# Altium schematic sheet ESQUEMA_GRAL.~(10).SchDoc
size A3
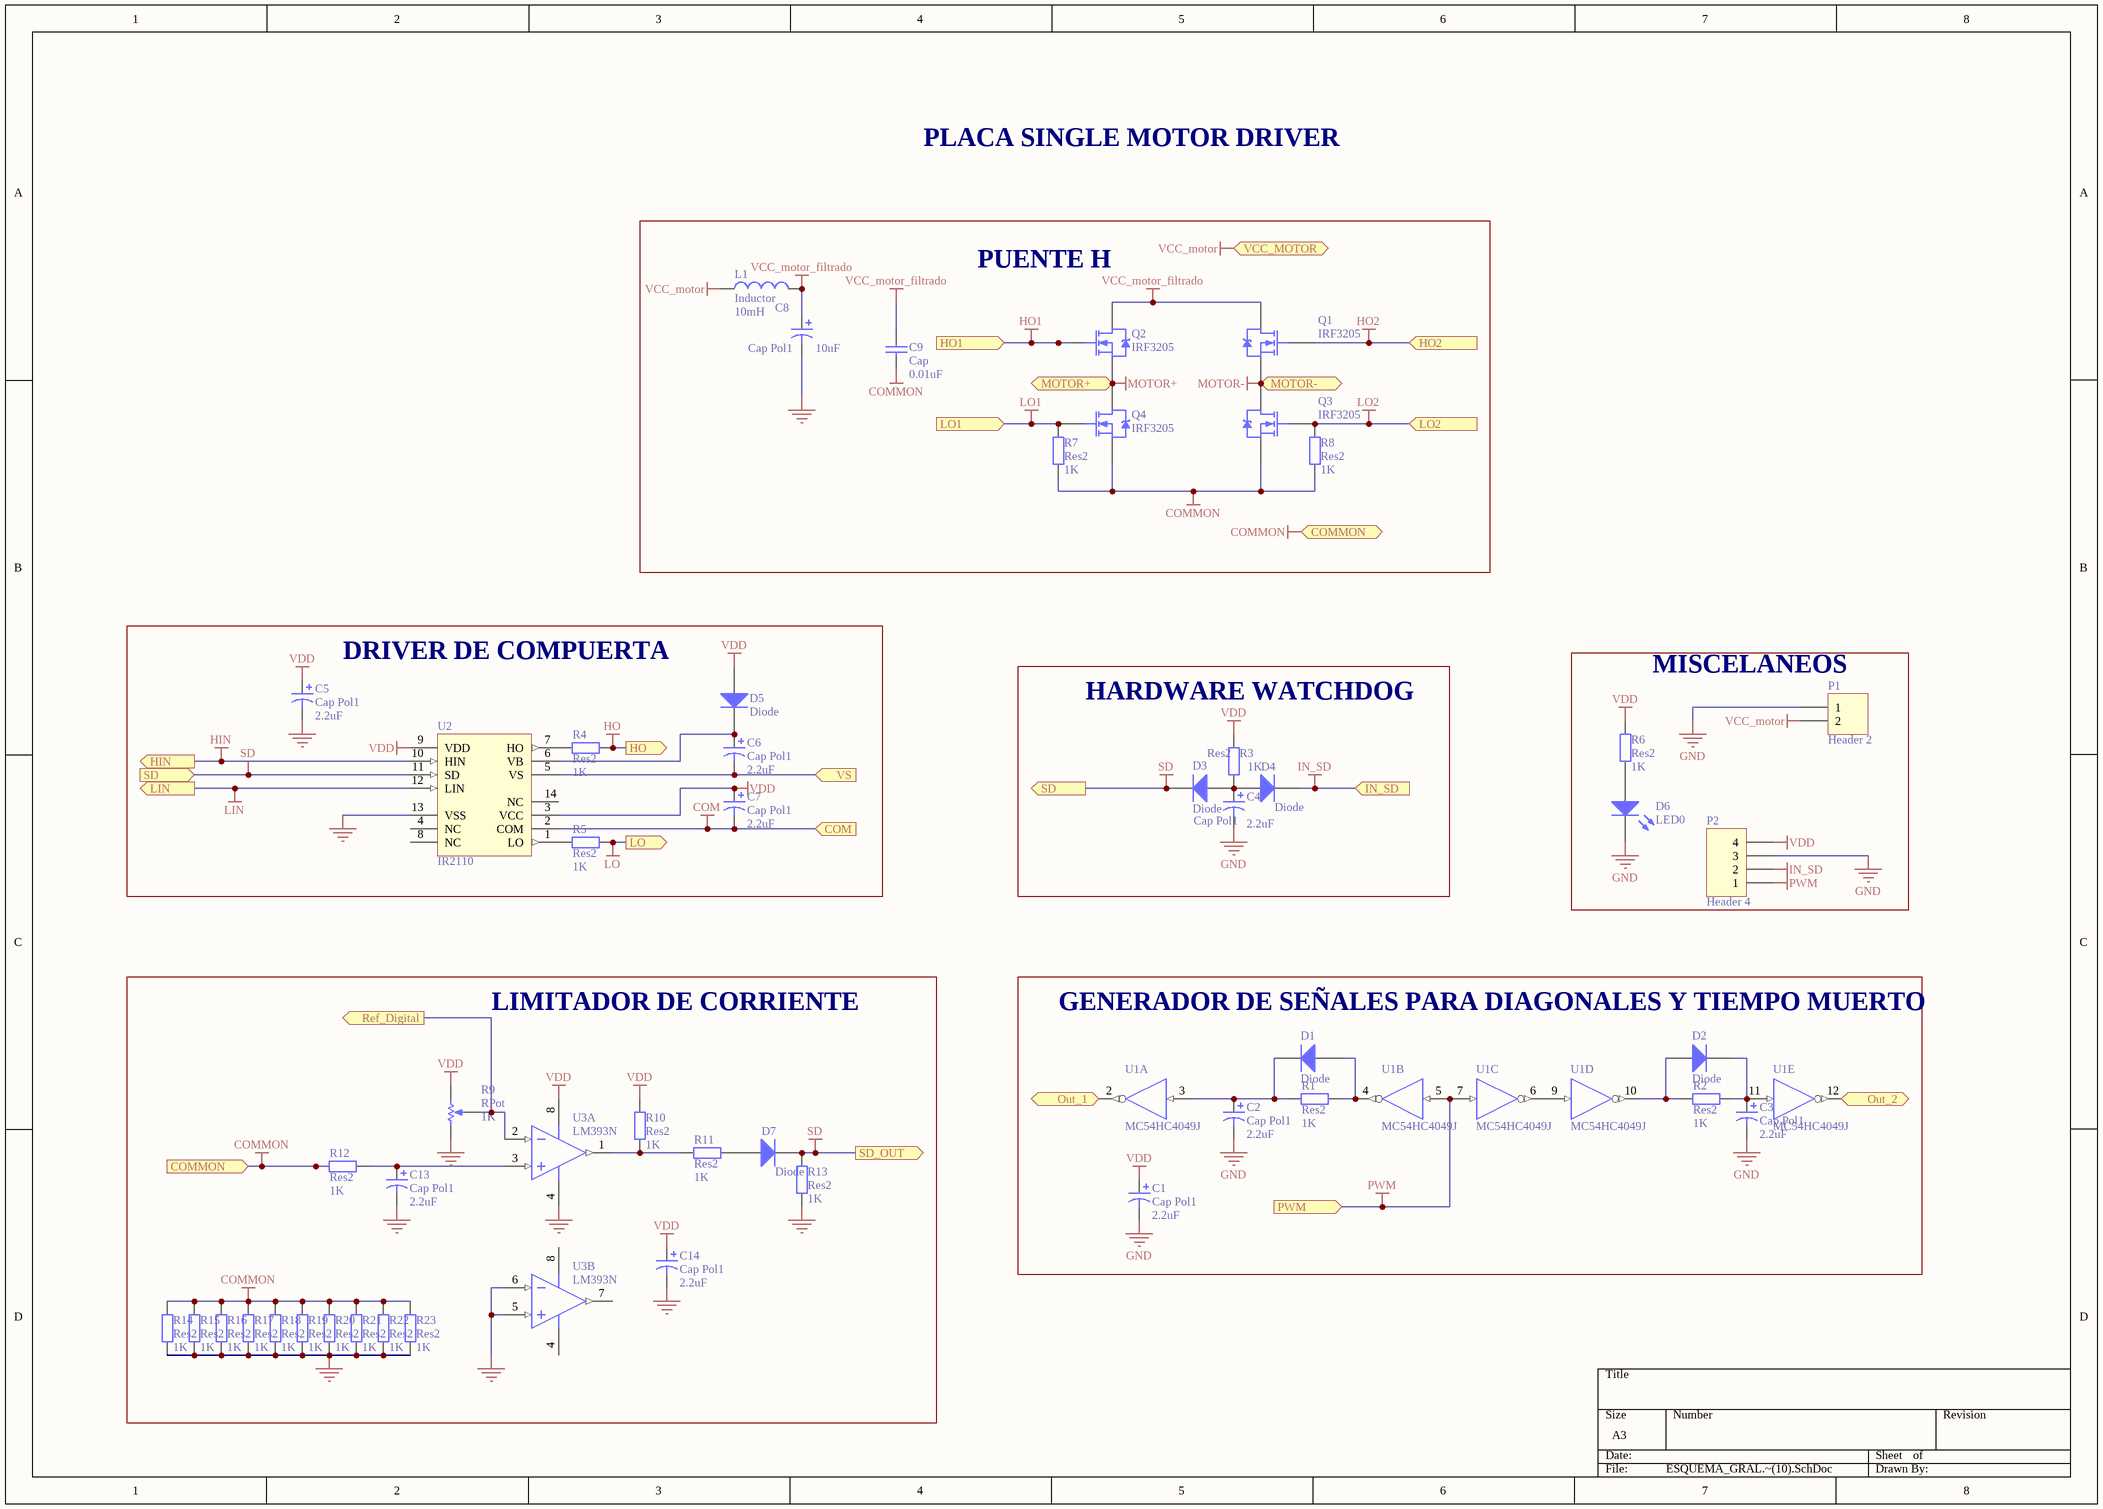
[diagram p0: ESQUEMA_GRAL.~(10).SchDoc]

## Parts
C1  Cap Pol1  value 2.2uF  [CAPPR2.5-6.3X5]
C2  Cap Pol1  value 2.2uF  [CAPPR2.5-6.3X5]
C3  Cap Pol1  value 2.2uF  [CAPPR2.5-6.3X5]
C4  Cap Pol1  value 2.2uF  [CAPPR2.5-6.3X5]
C5  Cap Pol1  value 2.2uF  [CAPPR2.5-6.3X5]
C6  Cap Pol1  value 2.2uF  [CAPPR2.5-6.3X5]
C7  Cap Pol1  value 2.2uF  [CAPPR2.5-6.3X5]
C8  Cap Pol1  value 10uF  [CAPPR5-13X16]
C9  Cap  value 0.01uF  [RAD-0.2]
C13  Cap Pol1  value 2.2uF  [CAPPR2.5-6.3X5]
C14  Cap Pol1  value 2.2uF  [CAPPR2.5-6.3X5]
D1  Diode  [DO-204AL]
D2  Diode  [DO-204AL]
D3  Diode  [DO-204AL]
D4  Diode  [DO-204AL]
D5  Diode  [DO-204AL]
D6  LED0  [CAPPR2.5-6.3X5]
D7  Diode  [DO-204AL]
L1  Inductor  value 10mH  [bobina_Choque]
P1  Header 2  [pwheader1x2]
P2  Header 4  [HDR1X5]
Q1  IRF3205  [TO-220AB]
Q2  IRF3205  [TO-220AB]
Q3  IRF3205  [TO-220AB]
Q4  IRF3205  [TO-220AB]
R1  Res2  value 1K  [AXIAL-0.3]
R2  Res2  value 1K  [AXIAL-0.3]
R3  Res2  value 1K  [AXIAL-0.3]
R4  Res2  value 1K  [AXIAL-0.3]
R5  Res2  value 1K  [AXIAL-0.3]
R6  Res2  value 1K  [AXIAL-0.3]
R7  Res2  value 1K  [AXIAL-0.3]
R8  Res2  value 1K  [AXIAL-0.3]
R9  RPot  value 1K  [VR5]
R10  Res2  value 1K  [AXIAL-0.3]
R11  Res2  value 1K  [AXIAL-0.3]
R12  Res2  value 1K  [AXIAL-0.3]
R13  Res2  value 1K  [AXIAL-0.3]
R14  Res2  value 1K  [AXIAL-0.4]
R15  Res2  value 1K  [AXIAL-0.4]
R16  Res2  value 1K  [AXIAL-0.4]
R17  Res2  value 1K  [AXIAL-0.4]
R18  Res2  value 1K  [AXIAL-0.4]
R19  Res2  value 1K  [AXIAL-0.4]
R20  Res2  value 1K  [AXIAL-0.4]
R21  Res2  value 1K  [AXIAL-0.4]
R22  Res2  value 1K  [AXIAL-0.4]
R23  Res2  value 1K  [AXIAL-0.4]
U1  MC54HC4049J  [620-09]  (parts A,B,C,D,E of 6)
U2  IR2110  [PDIP14]
U3  LM393N  [626-05]  (parts A,B of 2)

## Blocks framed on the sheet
PUENTE H: C8 C9 L1 Q1-Q4 R7 R8
DRIVER DE COMPUERTA: C5-C7 D5 R4 R5 U2
HARDWARE WATCHDOG: C4 D3 D4 R3
MISCELANEOS: D6 P1 P2 R6
LIMITADOR DE CORRIENTE: C13 C14 D7 R9-R23 U3
GENERADOR DE SEÑALES PARA DIAGONALES Y TIEMPO MUERTO: C1-C3 D1 D2 R1 R2 U1

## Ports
COM (in), COMMON (in), COMMON (out), HIN (out), HO1 (in), HO2 (in), HO (out), IN_SD (in), LIN (out), LO1 (in), LO2 (in), LO (out), MOTOR+ (bidir), MOTOR- (bidir), Out_1 (out), Out_2 (out), PWM (in), Ref_Digital (out), SD (in), SD (out), SD_OUT (out), VCC_MOTOR (in), VS (in)

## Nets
COM: C7.2 U2.2(COM) ; port COM
COMMON: C9.1 Q3.3(S) Q4.3(S) R7.1 R8.1 R12.1 R14.2 R15.2 R16.2 R17.2 R18.2 R19.2 R20.2 R21.2 R22.2 R23.2 ; port COMMON
GND: C1.2 C2.2 C3.2 C4.2 C5.2 C8.2 C13.2 C14.2 D6.2(K) P1.1 P2.3 R9.1(TOP) R13.1 R14.1 R15.1 R16.1 R17.1 R18.1 R19.1 R20.1 R21.1 R22.1 R23.1 U1.8(GND) U2.13(VSS) U3.4(GND) U3.5(IN+) U3.6(IN-)
HIN: U2.10(HIN) ; port HIN
HO: R4.2 ; port HO
HO1: Q2.1(G) ; port HO1
HO2: Q1.1(G) ; port HO2
IN_SD: D4.2(K) P2.2 ; port IN_SD
LIN: U2.12(LIN) ; port LIN
LO: R5.2 ; port LO
LO1: Q4.1(G) R7.2 ; port LO1
LO2: Q3.1(G) R8.2 ; port LO2
MOTOR+: Q2.3(S) Q4.2(D) ; port MOTOR+
MOTOR-: Q1.3(S) Q3.2(D) ; port MOTOR-
PWM: P2.1 U1.5(A) U1.7(A) ; port PWM
SD: D3.2(K) D7.2(K) R13.2 U2.11(SD) ; port SD, port SD_OUT
VCC_motor: L1.1 P1.2 ; port VCC_MOTOR
VCC_motor_filtrado: C8.1 C9.2 L1.2 Q1.2(D) Q2.2(D)
VDD: C1.1 C5.1 C7.1 C14.1 D5.1(A) P2.4 R3.2 R6.2 R9.2(BOT) R10.2 U1.1(VDD) U2.3(VCC) U2.9(VDD) U3.8(V+)
Out_1: U1.2(Y) ; port Out_1
Out_2: U1.12(Y) ; port Out_2
Ref_Digital: R9.3(TAP) U3.2(IN-) ; port Ref_Digital
VS: C6.2 U2.5(VS) ; port VS
NetC2_1: C2.1 D1.2(K) R1.1 U1.3(A)
NetC3_1: C3.1 D2.2(K) R2.2 U1.11(A)
NetC4_1: C4.1 D3.1(A) D4.1(A) R3.1
NetC6_1: C6.1 D5.2(K) U2.6(VB)
NetC13_1: C13.1 R12.2 U3.3(IN+)
NetD1_1: D1.1(A) R1.2 U1.4(Y)
NetD2_1: D2.1(A) R2.1 U1.10(Y)
NetD6_1: D6.1(A) R6.1
NetD7_1: D7.1(A) R11.2
NetR4_1: R4.1 U2.7(HO)
NetR5_1: R5.1 U2.1(LO)
NetR10_1: R10.1 R11.1 U3.1(OUT)
NetU1_6: U1.6(Y) U1.9(A)

Not connected (* = marked no-connect by the designer): U2 4(NC) 8(NC) 14(NC); U3 7(OUT)

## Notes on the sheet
- PLACA SINGLE MOTOR DRIVER

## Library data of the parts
C1-C8 C13 C14 = Cap Pol1: Polarized Capacitor (Radial)
C9 = Cap: Capacitor
D1-D5 D7 = Diode: Default Diode
D6 = LED0: Typical INFRARED GaAs LED
L1 = Inductor: Code_IEC: 1005
P1 = Header 2: Header, 2-Pin
P2 = Header 4: Header, 4-Pin
Q1-Q4 = IRF3205: HEXFET Power MOSFET; Note: Pin 2 is electrically connected to pin 4.
R1-R8 R10-R23 = Res2: Resistor
R9 = RPot: Potentiometer; Sim Note: Enter the Resistance value and the set point into parameter fields.; Set Position: 0.5
U1 = MC54HC4049J: Hex Inverting Buffer/Logic-Level Down Converter; Note: Pins 13 & 16 are NC and not drawn.
U2 = IR2110: High and Low Side Driver; Note: Pins 4, 8 and 14 are not connected
U3 = LM393N: Dual Comparator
